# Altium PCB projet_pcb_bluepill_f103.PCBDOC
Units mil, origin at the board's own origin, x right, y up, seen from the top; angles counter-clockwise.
Board outline 6205 x 2505 mil, 2 copper layers (TopLayer, BottomLayer); 12 components, 37 nets, 87 pads, 20 vias.
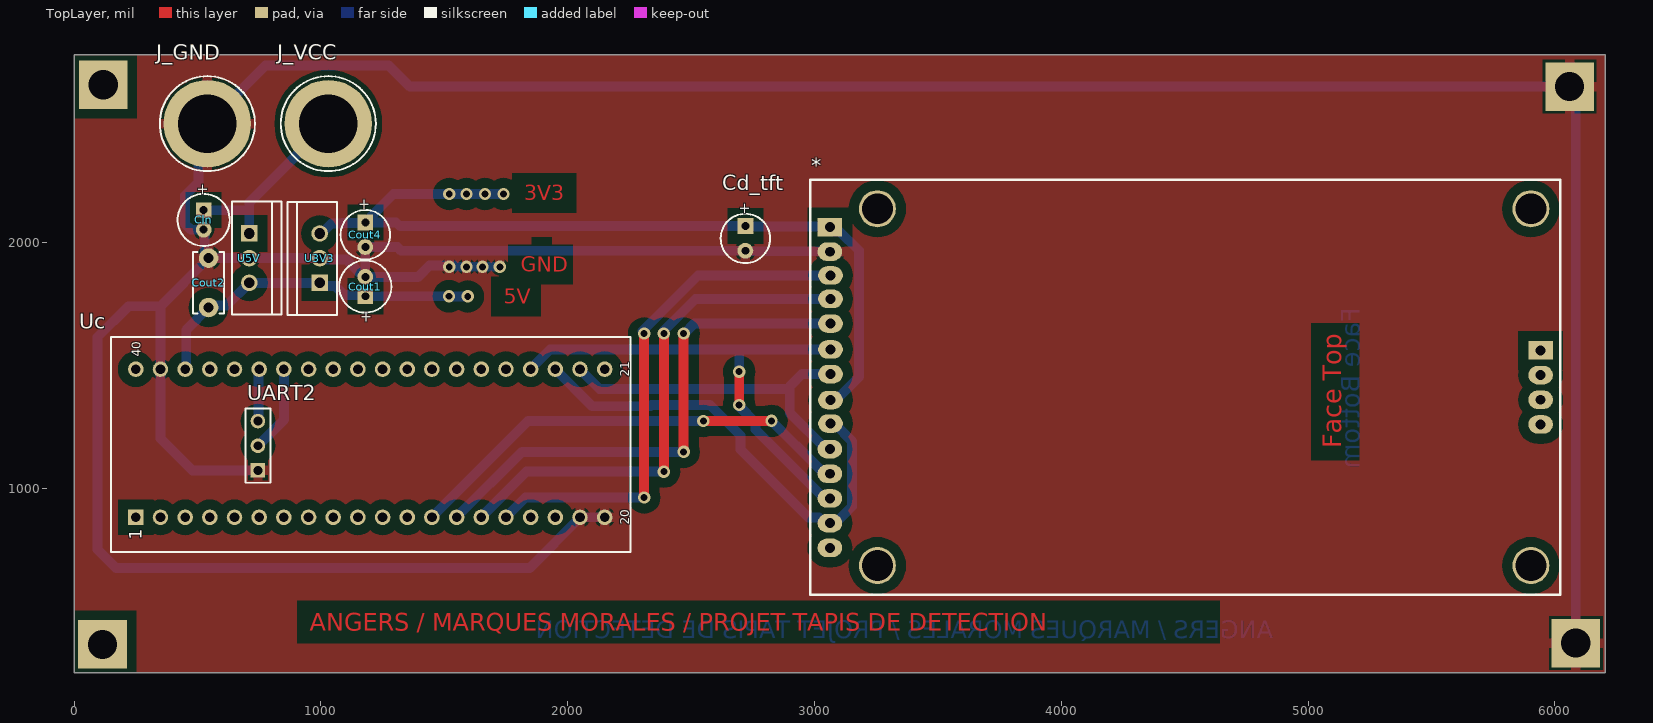
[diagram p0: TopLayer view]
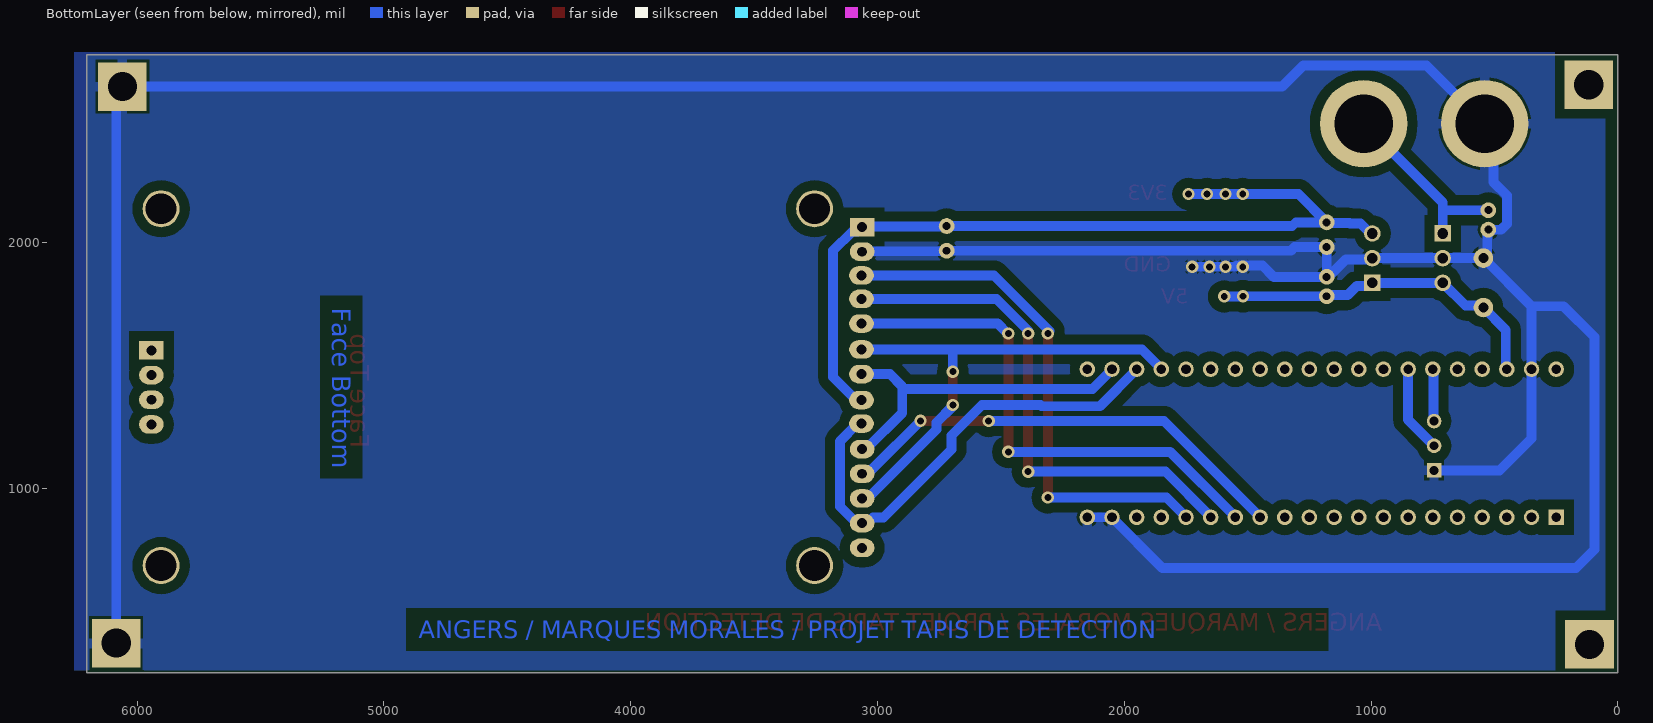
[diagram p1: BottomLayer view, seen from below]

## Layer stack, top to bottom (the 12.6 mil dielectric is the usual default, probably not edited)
TopSolder: solder mask 0.4, Solder Resist, Dk 3.5
TopLayer: signal copper 1.4
Dielectric1: core 12.6, FR-4, Dk 4.8
BottomLayer: signal copper 1.4
BottomSolder: solder mask 0.4, Solder Resist, Dk 3.5

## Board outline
0,255 0,2760 6205,2760 6205,255

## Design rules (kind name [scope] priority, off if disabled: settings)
Clearance PowerPlaneClearance [InNamedPolygon('Bot-GND') Or  InNamedPolygon('Top-GND')] p1: gap=40 ignorepadtopadclearanceinfootprint=FALSE except(0: Arc-Hole Track-Hole SMDPad-Hole THPad-Hole Via-Hole Fill-Hole Poly-Hole Region-Hole Text-Hole)
Clearance [All] p2: gap=20 ignorepadtopadclearanceinfootprint=TRUE except(0: Arc-Hole Track-Hole SMDPad-Hole THPad-Hole Via-Hole Fill-Hole Poly-Hole Region-Hole Text-Hole)
FabricationTestPointUsage TestPointUsage [All] p1: valid=0 allowmultiple=FALSE
FabricationTestpoint Testpoint [All] p1: side=3 testpointundercomponent=TRUE minsize=40 maxsize=100 preferedsize=60 minholesize=20 maxholesize=40 preferedholesize=32 testpointgrid=1 allowsidetop=TRUE allowsidebottom=TRUE usegrid=TRUE gridtolerance=0.01
Height [All] p1: minheight=0 maxheight=2000 prefheight=500
HoleSize [All] p1: absolutevalues=TRUE maxlimit=300 minlimit=11.81 maxpercent=80.000 minpercent=20.000
PlaneClearance [All] p1: clearance=40
PlaneConnect [All] p1: planeconnectstyle=Relief reliefexpansion=19.68 reliefentries=4 reliefconductorwidth=40 reliefairgap=19.68
PolygonConnect [All] p1: connectstyle=Relief reliefconductorwidth=40 reliefentries=4 polygonreliefangle="90 Angle" airgapwidth=10
RoomDefinition projet_pcb_bluepill_f103 [InComponentClass('projet_pcb_bluepill_f103')] p1: confinementstyle=ConfineIn formatcopy=TRUE lockcomponents=FALSE outline 8160,3655 9500,3655 9500,4130 8160,4130
RoutingVias [All] p1: holewidth=23.62 width=60 viastyle="Through Hole" minholewidth=23.62 minwidth=60 maxholewidth=23.62 maxwidth=60
SilkToSolderMaskClearance SilkscreenOverComponentPads [IsPad] p1: minsilkscreentomaskgap=10 clearancetoexposedcopper=TRUE
SolderMaskExpansion [All] p1: expansion=2
Width [All] p1: maxlimit=1000 minlimit=20 preferedwidth=40
23 further rules are at their usual default settings.

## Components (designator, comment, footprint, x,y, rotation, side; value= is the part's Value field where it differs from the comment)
* "2.4_TFT_TOUCH" 2.4_TFT_TOUCH 2982.56,571.22 r0 top
Cd_tft "10uF" CONDENSATEUR_POLARISE_ELECTROLYTIQUE_RADIAL_2.54/5.08 2720,2065 r270 top
Cin "CONDENSATEUR_POL_ELECTROLY_RAD_2.0/5.08" CONDENSATEUR_POLARISE_ELECTROLYTIQUE_RADIAL_2.0/5.08 525,2090 r270 top value=10µF/>25V
Cout1 "CONDENSATEUR_POL_ELECTROLY_RAD_2.0/5.08" CONDENSATEUR_POLARISE_ELECTROLYTIQUE_RADIAL_2.0/5.08 1180,1820 r90 top value=1µF/>10V
Cout2 "CONDENSATEUR_CER_RAD_5.08" CONDENSATEUR_CERAMIQUE_RADIAL_5.08 545,1935 r270 top value=100nF
Cout4 "CONDENSATEUR_POL_ELECTROLY_RAD_2.54/5.08" CONDENSATEUR_POLARISE_ELECTROLYTIQUE_RADIAL_2.54/5.08 1180,2080 r270 top value=4.7µF/63V
J_GND "DOUILLE BANANE 4mm" DOUILLE_BANANE_4mm 540,2480 r0 top
J_VCC "DOUILLE BANANE 4mm" DOUILLE_BANANE_4mm 1030,2480 r0 top
U3V3 "REGULATEUR_TO220_78XX" REGULATEUR_TO220_78XX 995,1935 r90 top
U5V "REGULATEUR_TO220_78XX" REGULATEUR_TO220_78XX 710,1935 r270 top
UART2 "BARRETTE3" HDR1X3 745,1075 r90 top
Uc "STM32F103C8T6/PCB_DIP40" STM32F103C8T6_DIP40 250,885 r90 top

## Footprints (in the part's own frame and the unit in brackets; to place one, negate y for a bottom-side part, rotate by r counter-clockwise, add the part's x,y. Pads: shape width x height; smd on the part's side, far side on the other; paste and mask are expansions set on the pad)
2.4_TFT_TOUCH [mil]
  round 150 hole 125: 0(272.44,118.11) 0(272.44,1563.78) 0(2920.47,118.11) 0(2920.47,1563.78)
  rect 100x75 hole 40: 1(80,1490) 18(2959.84,990)
  oval 100x75 hole 40: 2(80,1390) 3(82.44,1293.78) 4(82.44,1198.78) 5(82.44,1098.78) 6(82.44,993.78) 7(82.44,893.78) 8(82.44,788.78) 9(82.44,693.78) 10(80,590) 11(80,490) 12(80,390) 13(80,290) 14(80,190) 15(2959.84,690) 16(2959.84,790) 17(2959.84,890)
  silkscreen extent 0,-1 3039,1682, body extent 0,-1 3039,1681, height 650
CONDENSATEUR_CERAMIQUE_RADIAL_5.08 [mil] "CONDENSATEUR TRAVERSANT CERAMIQUE RADIAL ; DIMENSIONS : 3.17mm x 5.08mm"
  round 79 hole 40: 1(0,0) 2(200,0)
  silkscreen extent -25,-63 225,63, body extent -11,-43 209,42, height 148
CONDENSATEUR_POLARISE_ELECTROLYTIQUE_RADIAL_2.0/5.08 [mil] "CONDENSATEUR POLARISE ELECTROLYTIQUE RADIAL ; DIAMETRE : 5.08mm ; ESPACEMENT BROCHES : 2mm"
  rect 64x64 / inner round 64 / far side round 64 hole 32: 1(-39.37,0)
  round 64 hole 32: 2(39.37,0)
  silkscreen extent -106,-105 106,106, body extent -98,-98 98,98, height 433
CONDENSATEUR_POLARISE_ELECTROLYTIQUE_RADIAL_2.54/5.08 [mil] "CONDENSATEUR_POLARISE_ELECTROLYTIQUE_RADIAL ; DIAMETRE : 5.08mm ; ESPACEMENT BROCHES : 2.54mm"
  rect 64x64 / inner round 64 / far side round 64 hole 32: 1(0,0)
  round 64 hole 32: 2(100,0)
  silkscreen extent -50,-100 150,100, body extent -50,-101 149,98, height 446
DOUILLE_BANANE_4mm [mm] "DOUILLE BANANE ; DIAMETRE PASSAGE CONTACT = 4 mm ; DIAMETRE PERCAGE = 6 mm"
  round 9 hole 6: 1(0,0)
  silkscreen extent -4.89,-4.89 4.89,4.89, body extent -5.5,-5.6 5.63,5.53, height 4.79
HDR1X3 [mm] "Connector; Header; 3 Position"
  rect 1.5x1.5 hole 0.9: 1(0,0)
  round 1.5 hole 0.9: 2(2.54,0) 3(5.08,0)
  silkscreen extent -1.27,-1.27 6.35,1.27
REGULATEUR_TO220_78XX [mm] "BOITIER TO220 ; DIMENSIONS : 11.2mm x 4.7mm ; ESPACEMENT BROCHES : 2.54 mm"
  rect 1.7x1.7 hole 1.1: 1(-2.54,0)
  round 1.7 hole 1.1: 2(0,0) 3(2.54,0)
  silkscreen extent -5.83,-1.77 5.8,3.29, body extent -5.61,-1.59 5.61,3.1, height 19.33
STM32F103C8T6_DIP40 [mm] "STM32F103 monté sur DIP40"
  rect 1.6x1.6 hole 1: 1(0,0)
  round 1.6 hole 1: 2(0,-2.54) 3(0,-5.08) 4(0,-7.62) 5(0,-10.16) 6(0,-12.7) 7(0,-15.24) 8(0,-17.78) 9(0,-20.32) 10(0,-22.86) 11(0,-25.4) 12(0,-27.94) 13(0,-30.48) 14(0,-33.02) 15(0,-35.56) 16(0,-38.1) 17(0,-40.64) 18(0,-43.18) 19(0,-45.72) 20(0,-48.26) 21(15.24,-48.26) 22(15.24,-45.72) 23(15.24,-43.18) 24(15.24,-40.64) 25(15.24,-38.1) 26(15.24,-35.56) 27(15.24,-33.02) 28(15.24,-30.48) 29(15.24,-27.94) 30(15.24,-25.4) 31(15.24,-22.86) 32(15.24,-20.32) 33(15.24,-17.78) 34(15.24,-15.24) 35(15.24,-12.7) 36(15.24,-10.16) 37(15.24,-7.62) 38(15.24,-5.08) 39(15.24,-2.54) 40(15.24,0)
  silkscreen extent -3.56,-50.92 18.54,2.54, body extent -3.63,-51.04 18.37,6.1, height 20.63

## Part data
Cd_tft: library part Condensateur, "Capacitor"
Cin Cout1: "CONDENSATEUR POLARISE ELECTROLYTIQUE RADIAL 2.0/5.08"
Cout2: "CONDENSATEUR TRAVERSANT CERAMIQUE RADIAL 5.08mm"
Cout4: "CONDENSATEUR POLARISE ELECTROLYTIQUE RADIAL 2.54/5.08"
J_GND J_VCC: library part DOUILLE_BANANE_4mm, "DOUILLE BANANE 4 mm"
U3V3 U5V: "REGULATEUR DE TENSION POSITIVE 78XX BOITIER TO220", Package=(TO220)
UART2: "Header, 3-Pin"
Uc: "MICROCONTROLEUR 32 BITS - 72MHz - 34 I/O - 64 KO : FLASH - 20KO RAM - 10 CANAUX A/D 12 BITS - DIP40 - UART, SPI, I2C, USB, CAN", Package=DIP40

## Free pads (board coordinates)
  rect 196.85x196.85 hole 118.11: 1(118.11,2637.8) 2(115,370) 3(6085,375) 4(6060,2630)

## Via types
v1: diameter 50, hole 28, TopLayer to BottomLayer, 20 vias

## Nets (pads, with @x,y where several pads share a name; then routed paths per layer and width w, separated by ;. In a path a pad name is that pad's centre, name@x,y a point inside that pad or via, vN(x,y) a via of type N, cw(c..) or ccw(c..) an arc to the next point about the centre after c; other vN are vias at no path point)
+3V3: *.1 *.8 Cd_tft.1 Cout4.1 U3V3.3 | length 3524.9
  BottomLayer w40: U3V3.3 1002.29,2035 1042.29,2075 1085,2075 1088,2078 1178,2078 Cout4.1 ; v1(1740,2195) v1(1665,2195) v1(1590,2195) v1(1520,2195) 1295,2195 Cout4.1 ; *.8 3086.97,1360 3180,1453.03 3180,1965.88 3102.16,2043.72 3080.06,2043.72 *.1 3060.67,2063.11 2721.89,2063.11 Cd_tft.1 1320,2065 1305,2080 Cout4.1
+3V3_BP: Uc.40
+3V3_BP2: Uc.18
+5V: Cout1.1 Cout2.2 U3V3.1 U5V.3 Uc.38 | length 1403.6
  BottomLayer w40: Uc.38 454.4,1489.4 454.4,1644.4 Cout2.2 552.46,1742.46 617.46,1742.46 U5V.3 U3V3.1 1008.46,1821.54 1058.46,1821.54 1094.78,1785.22 1175.41,1785.22 Cout1.1 v1(1519.37,1780.63) 1520,1780 v1(1595,1780)
GND: *.2 Cd_tft.2 Cin.2 Cout1.2 Cout2.1 Cout4.2 J_GND.1 pad.3 pad.4 U3V3.2 U5V.2 UART2.1 Uc.19 Uc.20 Uc.39 | length 16454.4
  BottomLayer w40: UART2.1 480,1075 350,1205 Uc.39 350,1740 ; v1(1725,1900) v1(1655,1900) v1(1590,1900) 1548.65,1900 1543.65,1905 1520,1905 1440,1905 1394.37,1859.37 Cout1.2 ; Uc.20 Uc.19 2050,883.89 1846.11,680 170,680 95,755 95,1615 220,1740 350,1740 ; *.2 3060.67,1963.11 2721.89,1963.11 Cd_tft.2 1325,1965 1310,1980 Cout4.2 Cout1.2 ; pad.3 6085,2605 pad.4 ; pad.4@6090,2600 pad.4 ; 350,1740 Cout2.1 ; Cout2.1 545,1945.55 529.59,1960.96 529.59,2046.04 Cin.2 524.37,2050 473.43,2050 450,2073.43 450,2189.19 503.65,2242.83 503.65,2443.65 J_GND.1 775,2715 1275,2715 1360,2630 pad.4 ; Cout2.1 U5V.2 U3V3.2 1000.15,1929.85 1103.03,1929.85 1173.51,1859.37 Cout1.2
  other v1: 1520,1900
PA0_AN0: Uc.5
PA1_AN1: Uc.6
PA2: Uc.7
PA3: Uc.8
PA4: Uc.9
PA5: Uc.10
PA6: Uc.11
PA7: Uc.12
PA8: Uc.25
PA9: Uc.26
PA10: Uc.27
PA11: Uc.28
PA12: Uc.29
PA15: Uc.30
PB0_TOUCH-CS: *.11 Uc.13 | length 1864
  TopLayer w40: v1(2550,1275) 2825,1275 v1(2825.84,1275.84)
  BottomLayer w40: Uc.13 1450,886.11 1838.89,1275 v1(2550,1275) ; v1(2825.84,1275.84) 3017.96,1083.72 3018.09,1083.72 3040.59,1061.22 *.11
PB1_TFT-DC: *.5 Uc.14 | length 2122
  TopLayer w40: v1(2470,1150) v1(2470,1630)
  BottomLayer w40: Uc.14 1550,886.11 1813.89,1150 v1(2470,1150) ; v1(2470,1630) 2472.71,1630 2512.71,1670 *.5
PB3: Uc.31
PB4: Uc.32
PB5: Uc.33
PB6_U2TX: UART2.2 Uc.34 | length 353.5
  BottomLayer w40: UART2.2 850,1280 Uc.34
PB7_U2RX: UART2.3 Uc.35 | length 212.1
  BottomLayer w40: UART2.3 747.5,1277.5 747.5,1482.5 Uc.35
PB8_I2C_SCL: Uc.36
PB9_I2C_SDA: Uc.37
PB10_TFT-RESET: *.4 Uc.15 | length 2117.3
  TopLayer w40: v1(2390,1070) v1(2390,1630)
  BottomLayer w40: Uc.15 1650,886.11 1833.89,1070 v1(2390,1070) ; v1(2390,1630) 2390,1641.92 2518.08,1770 *.4
PB11_TFT-CS: *.3 Uc.16 | length 2126.8
  TopLayer w40: v1(2310,965) v1(2310,1630)
  BottomLayer w40: Uc.16 1750,886.11 1828.89,965 v1(2310,965) ; v1(2310,1630) 2310,1632.71 2302.96,1639.74 2528.22,1865 *.3
PB12: Uc.21
PB13_TFT-SCK: *.7 *.10 Uc.22 | length 1404.1
  BottomLayer w40: Uc.22 2050,1483.89 2128.89,1405 2890,1405 2900,1395 ; *.10 3046.68,1161.22 2900,1307.9 2900,1395 ; *.7 2950,1465 2900,1415 2900,1395
PB14_TFT-MISO: *.9 *.13 Uc.23 | length 1908.7
  BottomLayer w40: Uc.23 1950,1483.89 2098.89,1335 2335.41,1335 2340.41,1340 2576.92,1340 2700,1216.92 2700,1160 2976.28,883.72 3018.09,883.72 3040.59,861.22 *.13 3084.53,861.22 3107.03,883.72 3107.16,883.72 3152.56,929.12 3152.56,1193.32 3080.88,1265 *.9
PB15_TFT-MOSI: *.6 *.12 Uc.24 | length 2017.8
  TopLayer w40: v1(2695,1340) v1(2695,1475)
  BottomLayer w40: Uc.24 1850,1486.11 1928.89,1565 2695,1565 ; v1(2695,1340) 2695,1335 2760.84,1269.16 2760.84,1240.84 3017.96,983.72 3018.09,983.72 3040.59,961.22 *.12 ; v1(2695,1475) 2695,1565 ; *.6 2695,1565
PC14_OSC32: Uc.3
PC15_OSC32: Uc.4
VCC: Cin.1 J_VCC.1 U5V.1 | length 764.9
  BottomLayer w40: Cin.1 704.37,2129.37 710,2135 ; U5V.1 710,2135 ; J_VCC.1 710,2160 710,2135
pads on no net: *.0 *.14 *.15 *.16 *.17 *.18 Uc.1 Uc.2 Uc.17

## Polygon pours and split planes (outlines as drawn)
GND on BottomLayer "Bot-GND" (solid, pour order 5): 50.61,2770 6255.62,2770 6255.62,265 50.61,265
GND on TopLayer "Top-GND" (solid, pour order 4): 0,2760 6205,2760 6205,255 5,255

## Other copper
TopLayer:
  text "3V3" at 1825,2170 h60
  text "GND" at 1810,1880 h60
  text "5V" at 1740,1750 h60
  text "Face Top" at 5135,1165 h75 r90
  text "ANGERS / MARQUES MORALES / PROJET TAPIS DE DETECTION" at 955,425 h70.87
BottomLayer:
  text "Face Bottom" at 5210,1735 h75 r90
  text "ANGERS / MARQUES MORALES / PROJET TAPIS DE DETECTION" at 4860,395 h70.87

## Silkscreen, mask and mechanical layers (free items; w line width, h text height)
Mechanical1:
  the board outline again, w20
